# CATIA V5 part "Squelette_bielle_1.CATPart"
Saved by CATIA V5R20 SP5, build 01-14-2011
Part number: Squelette_bielle_1
Publications: "Longueur_bielle", "Point.1", "Point.2", "Droite.1", "Droite.2", "Droite.3", "Plan xy", "Plan yz", "Plan zx"
Bounding box of the stored display mesh (mm): x 0 to 104, y 0 to 20, z 0 to 0
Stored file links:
  C:\Users\MARLENE\Documents\IFMA\S3\IAO\Copie de CAO\Squelette_bielle_1.CATPart
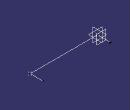
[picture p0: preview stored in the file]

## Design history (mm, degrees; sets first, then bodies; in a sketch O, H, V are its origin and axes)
Parameters
  Longueur_bielle = 104 mm
Set1
  Point1: (0, 0, 0)
  Point2: (104 {= Longueur_bielle}, 0, 0)
  Line1: type PtPt, FirstPoint Point1, SecondPoint Point2
  Line2: type PtDir, RefPoint Point2, Direction zx-plane, Start 0, End 20
  Line3: type PtDir, RefPoint Point1, Direction zx-plane, Start 0, End 20
  Plane1: type Offset, RefPlane zx-plane, Offset 6
Body1 (main body)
